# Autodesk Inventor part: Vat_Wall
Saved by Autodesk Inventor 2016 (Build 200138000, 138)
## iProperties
Created: 2016-01
Part Number: Vat_Wall
Material: Generic
Document SubType Name: Modeling
Designer: John
Density: 1 g/cm^3
Appearance: Default
Author: John
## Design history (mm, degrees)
feature "SOLID1"
body "Solid1"
